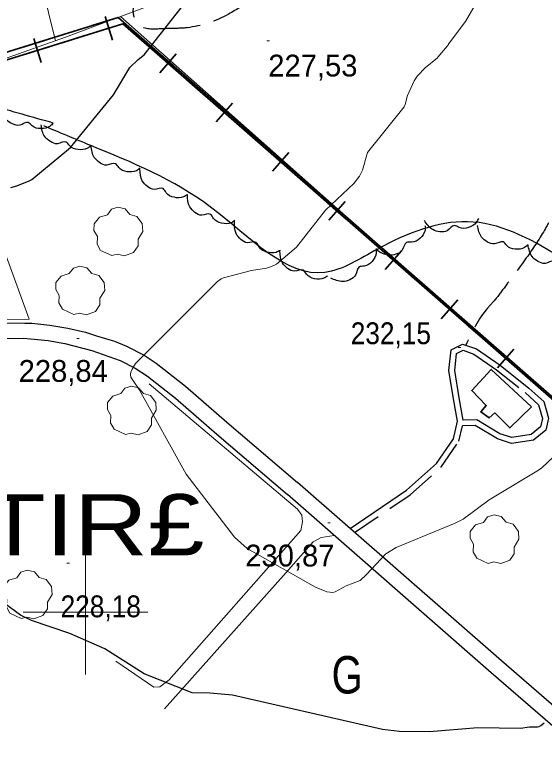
# Model space of a CAD drawing. Extents: x 480269 to 484877, y 4383588 to 4386804.
# Drawn here: x 482971.7 to 483184, y 4384938.8 to 4385239.6 of the extents above; entities that cross this region are included whole.
import ezdxf
from ezdxf.enums import TextEntityAlignment as Align

# ---------------------------------------------------------------- set-up
doc = ezdxf.new("R2010")
doc.units = 0
doc.header["$LTSCALE"] = 3.8
doc.linetypes.add('LONG_DASHED', pattern=[7.5, 6, -1.5])
doc.linetypes.add('MEDIUM_DASHED', pattern=[4.5, 3, -1.5])
for name, color, linetype, lineweight in [('1', 7, 'Continuous', 13), ('27', 7, 'Continuous', 25), ('29', 7, 'Continuous', 13), ('34', 7, 'Continuous', 35), ('37', 7, 'Continuous', 25), ('38', 7, 'Continuous', 25), ('47', 7, 'Continuous', 35), ('51', 7, 'Continuous', 13), ('7', 7, 'Continuous', 13), ('8', 7, 'Continuous', 25), ('9', 7, 'Continuous', 13)]:
    doc.layers.add(name, color=color, linetype=linetype, lineweight=lineweight)
doc.layers.add('31', color=7, linetype='Continuous')
doc.layers.add('5', color=7, linetype='Continuous')

msp = doc.modelspace()

# ---------------------------------------------------------------- linework, layer by layer
at = {"layer": '1'}
for p, q in [((483000, 4385025), (483000, 4384975)), ((482975, 4385000), (483025, 4385000))]:
    msp.add_line(p, q, dxfattribs=at)
at = {"layer": '27'}
for points in [[(482987.06, 4385196.22), (482962.01, 4385203.27), (482933.82, 4385208.75), (482918.16, 4385210.32), (482910.33, 4385217.37), (482911.12, 4385227.55), (482911.12, 4385236.17), (482900.16, 4385244), (482857.87, 4385258.89), (482836.73, 4385270.64), (482824.21, 4385265.15), (482832.82, 4385247.14), (482820.29, 4385239.3), (482767.05, 4385239.3), (482715.37, 4385240.87), (482694.23, 4385249.49), (482675.44, 4385265.94), (482679.36, 4385287.09), (482678.57, 4385302.75), (482650.39, 4385311.37), (482636.29, 4385330.17), (482633.95, 4385351.32), (482617.5, 4385368.55), (482588.53, 4385379.52), (482572.87, 4385393.62), (482558.78, 4385411.63), (482539.21, 4385429.65), (482525.9, 4385448.45), (482516.5, 4385468.82), (482492.23, 4385501.72), (482482.83, 4385522.08), (482488.31, 4385537.75), (482533.73, 4385569.87), (482542.34, 4385576.13)], [(482987.06, 4385196.22), (482985.78, 4385194.99), (482982.12, 4385194.01), (482978.59, 4385195.11), (482977.04, 4385196.45), (482973.66, 4385195.36), (482970.72, 4385195.88), (482968.23, 4385197.59), (482966.17, 4385202.11)], [(483002.19, 4385187.17), (483000.77, 4385186.11), (482997.02, 4385185.57), (482993.65, 4385187.1), (482992.27, 4385188.61), (482988.78, 4385187.94), (482985.93, 4385188.8), (482983.66, 4385190.81), (482982.17, 4385195.54)], [(483727.16, 4385128.45), (483702.11, 4385129.24), (483649.65, 4385135.5), (483626.16, 4385132.37), (483588.58, 4385137.07), (483567.44, 4385128.45), (483561.17, 4385115.92), (483569.79, 4385101.04), (483587.01, 4385090.07), (483591.71, 4385074.4), (483579.96, 4385046.2), (483570.57, 4385028.19), (483559.61, 4385025.84), (483542.38, 4385040.72), (483515.76, 4385050.9), (483496.19, 4385065), (483481.31, 4385072.05), (483441.38, 4385059.52), (483420.24, 4385048.55), (483385, 4385062.65), (483357.6, 4385086.15), (483334.89, 4385110.44), (483327.07, 4385140.2), (483309.84, 4385151.17), (483298.1, 4385151.17), (483281.65, 4385134.72), (483253.47, 4385133.15), (483239.37, 4385137.85), (483220.58, 4385130.8), (483190.05, 4385142.55), (483153.25, 4385156.65), (483117.23, 4385145.69), (483096.09, 4385136.29), (483050.68, 4385162.14), (483002.13, 4385187.2), (482983.34, 4385195.04)], [(483021.92, 4385178.13), (483020.46, 4385177.12), (483016.69, 4385176.71), (483013.38, 4385178.35), (483012.06, 4385179.91), (483008.54, 4385179.36), (483005.72, 4385180.32), (483003.53, 4385182.4), (483002.2, 4385187.18)], [(483040.85, 4385167.49), (483039.33, 4385166.57), (483035.54, 4385166.43), (483032.35, 4385168.29), (483031.13, 4385169.94), (483027.59, 4385169.63), (483024.84, 4385170.78), (483022.8, 4385173.01), (483021.8, 4385177.87)], [(483059.91, 4385157.12), (483058.39, 4385156.2), (483054.6, 4385156.06), (483051.41, 4385157.92), (483050.19, 4385159.57), (483046.65, 4385159.25), (483043.9, 4385160.41), (483041.86, 4385162.64), (483040.86, 4385167.5)], [(483157.65, 4385157.93), (483156.81, 4385156.37), (483153.62, 4385154.32), (483149.93, 4385154.29), (483148.04, 4385155.1), (483145.15, 4385153.02), (483142.2, 4385152.61), (483139.3, 4385153.49), (483135.97, 4385157.16)], [(483078.05, 4385145.16), (483076.46, 4385144.36), (483072.67, 4385144.48), (483069.62, 4385146.56), (483068.52, 4385148.29), (483064.97, 4385148.22), (483062.3, 4385149.57), (483060.42, 4385151.94), (483059.76, 4385156.85)], [(483136.34, 4385154.95), (483136.23, 4385153.17), (483134.19, 4385149.97), (483130.85, 4385148.4), (483128.8, 4385148.34), (483127.04, 4385145.25), (483124.53, 4385143.64), (483121.53, 4385143.22), (483116.97, 4385145.16)], [(483177.55, 4385147.39), (483176.17, 4385146.29), (483172.43, 4385145.63), (483169.02, 4385147.05), (483167.59, 4385148.52), (483164.13, 4385147.74), (483161.24, 4385148.51), (483158.92, 4385150.45), (483157.28, 4385155.13)], [(483116.56, 4385145.9), (483116.65, 4385144.13), (483114.97, 4385140.73), (483111.82, 4385138.8), (483109.79, 4385138.52), (483108.38, 4385135.25), (483106.06, 4385133.38), (483103.13, 4385132.64), (483098.38, 4385134.07)], [(483197.79, 4385139.57), (483196.4, 4385138.46), (483192.66, 4385137.82), (483189.26, 4385139.25), (483187.84, 4385140.73), (483184.37, 4385139.96), (483181.49, 4385140.75), (483179.17, 4385142.69), (483177.55, 4385147.38)], [(483097.16, 4385134.92), (483095.66, 4385133.98), (483091.87, 4385133.77), (483088.65, 4385135.57), (483087.4, 4385137.2), (483083.87, 4385136.82), (483081.1, 4385137.93), (483079.01, 4385140.12), (483077.93, 4385144.96)]]:
    msp.add_spline(points, degree=3, dxfattribs=at)
at = {"layer": '29'}
for points in [[(483010.6, 4385143.05), (483006.06, 4385145.17), (483004.65, 4385147.71), (483004.75, 4385150.69), (483003.38, 4385153.1), (483003.42, 4385155.85), (483005.58, 4385158.45), (483008.77, 4385159.45), (483010.42, 4385161.64), (483012.99, 4385162.47), (483015.85, 4385161.82), (483017.8, 4385159.55), (483020.61, 4385158.73), (483022.74, 4385155.88), (483022.98, 4385152.75), (483021.1, 4385149.6), (483021.1, 4385146.92), (483019.28, 4385144.31), (483015.66, 4385142.97), (483012.89, 4385143.6)], [(482995.31, 4385119.42), (482990.77, 4385121.54), (482989.36, 4385124.08), (482989.46, 4385127.06), (482988.09, 4385129.47), (482988.13, 4385132.22), (482990.29, 4385134.82), (482993.48, 4385135.82), (482995.13, 4385138.01), (482997.7, 4385138.84), (483000.56, 4385138.19), (483002.51, 4385135.92), (483005.32, 4385135.1), (483007.45, 4385132.25), (483007.69, 4385129.12), (483005.81, 4385125.97), (483005.81, 4385123.29), (483003.99, 4385120.68), (483000.37, 4385119.34), (482997.6, 4385119.97)], [(483016.02, 4385071.31), (483011.48, 4385073.43), (483010.07, 4385075.97), (483010.17, 4385078.95), (483008.8, 4385081.36), (483008.84, 4385084.11), (483011, 4385086.71), (483014.19, 4385087.71), (483015.84, 4385089.9), (483018.41, 4385090.73), (483021.27, 4385090.08), (483023.22, 4385087.81), (483026.03, 4385086.99), (483028.16, 4385084.14), (483028.4, 4385081.01), (483026.52, 4385077.86), (483026.52, 4385075.18), (483024.7, 4385072.57), (483021.08, 4385071.23), (483018.31, 4385071.86)], [(483161.53, 4385019.64), (483156.99, 4385021.76), (483155.58, 4385024.3), (483155.68, 4385027.28), (483154.31, 4385029.69), (483154.35, 4385032.44), (483156.51, 4385035.04), (483159.7, 4385036.04), (483161.35, 4385038.23), (483163.92, 4385039.06), (483166.78, 4385038.41), (483168.73, 4385036.14), (483171.54, 4385035.32), (483173.67, 4385032.47), (483173.91, 4385029.34), (483172.03, 4385026.19), (483172.03, 4385023.51), (483170.21, 4385020.9), (483166.59, 4385019.56), (483163.82, 4385020.19)], [(482974.23, 4384997.48), (482969.69, 4384999.6), (482968.28, 4385002.14), (482968.38, 4385005.12), (482967.01, 4385007.53), (482967.05, 4385010.28), (482969.21, 4385012.88), (482972.4, 4385013.88), (482974.05, 4385016.07), (482976.62, 4385016.9), (482979.48, 4385016.25), (482981.43, 4385013.98), (482984.24, 4385013.16), (482986.37, 4385010.31), (482986.61, 4385007.18), (482984.73, 4385004.03), (482984.73, 4385001.35), (482982.91, 4384998.74), (482979.29, 4384997.4), (482976.52, 4384998.03)]]:
    msp.add_lwpolyline(points, close=True, dxfattribs=at)
at = {"layer": '34'}
for p, q in [((483010.82, 4385229.47), (483007.86, 4385239.02)), ((483012.23, 4385238.28), (483002.68, 4385235.31)), ((483012.23, 4385238.28), (483002.68, 4385235.31)), ((483014.11, 4385235.73), (483004.56, 4385232.76)), ((483025.59, 4385226.75), (483018.06, 4385233.33)), ((482982.18, 4385220.57), (482979.22, 4385230.12)), ((482999.79, 4385231.28), (482990.24, 4385228.31)), ((482983.59, 4385229.38), (482974.04, 4385226.41)), ((482983.59, 4385229.38), (482974.04, 4385226.41)), ((482985.47, 4385226.83), (482975.92, 4385223.86)), ((483035.01, 4385219.43), (483027.48, 4385226.01)), ((483035.01, 4385219.43), (483027.48, 4385226.01)), ((483036.89, 4385216.88), (483029.36, 4385223.46)), ((483029.83, 4385216.4), (483036.41, 4385223.93)), ((483048.18, 4385207.02), (483040.65, 4385213.6)), ((483057.59, 4385199.7), (483050.06, 4385206.28)), ((483057.59, 4385199.7), (483050.06, 4385206.28)), ((483059.47, 4385197.15), (483051.94, 4385203.73)), ((483052.42, 4385196.67), (483059, 4385204.2)), ((483070.76, 4385187.29), (483063.23, 4385193.87)), ((483080.18, 4385179.97), (483072.65, 4385186.55)), ((483080.18, 4385179.97), (483072.65, 4385186.55)), ((483075, 4385176.94), (483081.58, 4385184.47)), ((483082.06, 4385177.42), (483074.53, 4385184)), ((483093.35, 4385167.56), (483085.82, 4385174.13)), ((483102.76, 4385160.24), (483095.23, 4385166.82)), ((483102.76, 4385160.24), (483095.23, 4385166.82)), ((483104.64, 4385157.69), (483097.11, 4385164.27)), ((483097.59, 4385157.21), (483104.17, 4385164.74)), ((483115.93, 4385147.82), (483108.4, 4385154.4)), ((483125.35, 4385140.51), (483117.82, 4385147.08)), ((483125.35, 4385140.51), (483117.82, 4385147.08)), ((483127.23, 4385137.96), (483119.7, 4385144.53)), ((483120.17, 4385137.48), (483126.75, 4385145.01)), ((483138.52, 4385128.09), (483130.99, 4385134.67)), ((483147.93, 4385120.77), (483140.4, 4385127.35)), ((483147.93, 4385120.77), (483140.4, 4385127.35)), ((483149.81, 4385118.22), (483142.28, 4385124.8)), ((483142.76, 4385117.75), (483149.34, 4385125.28)), ((483161.1, 4385108.36), (483153.57, 4385114.94)), ((483170.52, 4385101.04), (483162.99, 4385107.62)), ((483170.52, 4385101.04), (483162.99, 4385107.62)), ((483172.4, 4385098.49), (483164.87, 4385105.07)), ((483165.34, 4385098.02), (483171.92, 4385105.55)), ((483183.69, 4385088.63), (483176.16, 4385095.21))]:
    msp.add_line(p, q, dxfattribs=at)
for points in [[(483464.12, 4384844.55), (483013.12, 4385238.55), (482720.12, 4385147.55)], [(483464.12, 4384844.55), (483013.12, 4385238.55), (482720.12, 4385147.55)], [(483466, 4384842), (483015, 4385236), (482722, 4385145)]]:
    msp.add_lwpolyline(points, dxfattribs=at)
at = {"layer": '37'}
for points in [[(482750.83, 4385043.15), (482792.84, 4385058.2), (482913.56, 4385101.78), (482939.57, 4385111.12), (482955.6, 4385115), (482967.37, 4385116.08), (482975.61, 4385116.03), (482978.44, 4385115.95), (482985.74, 4385115.14), (482992.89, 4385114), (482999.97, 4385112.36), (483004.37, 4385110.93), (483011.65, 4385108.69), (483016.47, 4385106.74), (483023.56, 4385103.12), (483028.35, 4385099.96), (483040.15, 4385090.7), (483056.73, 4385076.2), (483085.09, 4385052.01)], [(482752.89, 4385037.24), (482794.96, 4385052.31), (482915.68, 4385095.89), (482941.37, 4385105.12), (482956.63, 4385108.81), (482967.62, 4385109.83), (482975.06, 4385109.91), (482977.98, 4385109.7), (482985.07, 4385109.02), (482991.66, 4385107.85), (483002.53, 4385104.94), (483013.88, 4385101.02), (483019.88, 4385097.89), (483024.85, 4385094.76), (483036.16, 4385085.88), (483052.64, 4385071.47), (483081.03, 4385047.25)], [(483278.04, 4384763.7), (483388.31, 4384775.37), (483396.25, 4384777.5), (483401.8, 4384780.35), (483406.67, 4384784.64), (483410.91, 4384790.59), (483412.8, 4384795.66), (483413.03, 4384800.96), (483412.9, 4384805.24), (483411.9, 4384810.34), (483409.49, 4384815.21), (483404.8, 4384820.61), (483398.46, 4384824.66), (483380.67, 4384830.95), (483329.04, 4384849.79), (483319.89, 4384854.08), (483310.58, 4384858.59), (483303.26, 4384863.02), (483294.69, 4384869.69), (483265.36, 4384895.28), (483166.86, 4384980.49), (483085.09, 4385052.01)], [(483277.39, 4384769.88), (483387.17, 4384781.5), (483394, 4384783.33), (483398.27, 4384785.53), (483402.03, 4384788.83), (483405.38, 4384793.53), (483406.63, 4384796.91), (483406.81, 4384801), (483406.7, 4384804.54), (483405.96, 4384808.33), (483404.27, 4384811.74), (483400.69, 4384815.85), (483395.71, 4384819.03), (483378.57, 4384825.1), (483326.65, 4384844.04), (483317.22, 4384848.47), (483307.61, 4384853.12), (483299.73, 4384857.89), (483290.74, 4384864.89), (483261.29, 4384890.58), (483162.79, 4384975.79), (483081.03, 4385047.25)]]:
    msp.add_lwpolyline(points, dxfattribs=at)
at = {"layer": '38'}
msp.add_lwpolyline([(483106.14, 4385033.6), (483128.84, 4385049.01), (483140.8, 4385059.65), (483147.64, 4385069.6), (483149.27, 4385076.64), (483147.61, 4385085.57), (483145.83, 4385096.92), (483146.75, 4385105.22), (483151.31, 4385107.6), (483156.89, 4385105.64), (483166.32, 4385099.13), (483177.88, 4385089.96), (483183.85, 4385084.49), (483185.81, 4385077.82), (483184.64, 4385073.09), (483179.73, 4385069.06), (483170.92, 4385067.76), (483165.33, 4385069.51), (483156.38, 4385074.9), (483151.22, 4385074.77)], dxfattribs=at)
at = {"layer": '38', "linetype": 'MEDIUM_DASHED'}
msp.add_lwpolyline([(483151.54, 4385077.1), (483149.89, 4385085.96), (483148.16, 4385096.97), (483148.92, 4385103.74), (483151.49, 4385105.08), (483155.83, 4385103.56), (483164.94, 4385097.26), (483176.38, 4385088.2), (483181.81, 4385083.22), (483183.41, 4385077.77), (483182.57, 4385074.39), (483178.76, 4385071.25), (483171.11, 4385070.13), (483166.29, 4385071.64), (483157, 4385077.23)], close=True, dxfattribs=at)
msp.add_lwpolyline([(483107.95, 4385032.02), (483130.27, 4385047.18), (483142.55, 4385058.11), (483149.8, 4385068.65), (483151.22, 4385074.77)], dxfattribs=at)
at = {"layer": '38', "linetype": 'LONG_DASHED'}
for points in [[(483231.71, 4385291.72), (483227.07, 4385289.88), (483224.76, 4385288.84), (483210.03, 4385287.11), (483195.81, 4385285.01), (483189.41, 4385283.56), (483174.85, 4385274.14), (483167.81, 4385267.95), (483162.72, 4385266.81), (483147.6, 4385269.26), (483135.17, 4385269.21), (483119.25, 4385265.45), (483108.31, 4385261.73), (483096.96, 4385258.93), (483089.15, 4385256.51), (483079.32, 4385250.68), (483067.26, 4385245.51), (483057.36, 4385239.88), (483040.77, 4385234.46), (483034.16, 4385234.12), (483030.67, 4385234.03), (483022.01, 4385235.14), (483019.28, 4385239.84), (483021.59, 4385248.25), (483027.91, 4385256.06), (483032.96, 4385259.9), (483035.22, 4385262.44), (483041.85, 4385273.53), (483044.53, 4385281.27), (483044.91, 4385281.85)], [(483224.5, 4385288.79), (483215.18, 4385270.41), (483210.92, 4385259.97), (483207.19, 4385254.06), (483203.43, 4385244.09), (483201.5, 4385230.63), (483197.81, 4385218.11), (483194.75, 4385214.07), (483190.62, 4385208.45), (483188.08, 4385196.33), (483190.37, 4385184.14), (483191.32, 4385176.01), (483191.42, 4385172.87), (483187.92, 4385160.4), (483184.53, 4385153.91), (483177.42, 4385142.89), (483168.21, 4385130.43), (483163.61, 4385124.56), (483161.24, 4385121.93), (483152.6, 4385107.16)]]:
    msp.add_spline(points, degree=3, dxfattribs=at)
at = {"layer": '47'}
msp.add_lwpolyline([(483178.95, 4385082.35), (483170.29, 4385073.92), (483164.19, 4385080), (483162.02, 4385077.94), (483158.65, 4385080.4), (483160.8, 4385082.99), (483154.96, 4385088.98), (483162.79, 4385097.44)], close=True, dxfattribs=at)
at = {"layer": '51'}
msp.add_line((483014.09, 4385239.01), (483086.9, 4385174.35), dxfattribs=at)
for points in [[(482404.1, 4385677.73), (482302.92, 4385714.75), (482302.94, 4385713.84), (482359.86, 4385638.29), (482423.37, 4385556.01), (482487.7, 4385471.02), (482548.28, 4385389.71), (482609.6, 4385302.12), (482658.45, 4385236.36), (482731.86, 4385137.6), (482793.32, 4385159.98), (482893.05, 4385195.69), (482991.91, 4385230.66), (483071.52, 4385260.62), (483095.48, 4385269.3)], [(482888.55, 4385653.3), (482898.36, 4385609.21), (482918.04, 4385522.13), (482930.07, 4385471.8), (482937.62, 4385437.48), (482942.19, 4385414.98), (482947.25, 4385388.98), (482952.06, 4385372.32), (482962.15, 4385333.18), (482987.92, 4385229.25)], [(482942.5, 4385213.18), (482977.38, 4385117.59), (482963.03, 4385117.44), (482951.62, 4385115.72), (482942.17, 4385113.17), (482923.87, 4385106.77), (482898.56, 4385097.91), (482807.23, 4385064.72), (482757.84, 4385047.5), (482755.28, 4385047.9), (482753.59, 4385049.34), (482751.71, 4385051.55), (482745.16, 4385065.2), (482737.85, 4385077), (482727.91, 4385087.2), (482717.9, 4385095.04), (482705.8, 4385100.41), (482691.98, 4385104.02), (482677.18, 4385105.47), (482666.61, 4385104.38), (482649.93, 4385100.31), (482731.86, 4385137.6)], [(483086.9, 4385174.35), (483229.36, 4385048.09), (483347.1, 4384943.87), (483471.81, 4384834.33), (483524.94, 4384677.86), (483563.45, 4384563.55), (483629, 4384366.69), (483674.71, 4384233.19), (483700.1, 4384145.59)], [(483012.13, 4384980.46), (483027.38, 4384970.02), (483029.79, 4384970.18), (483033.55, 4384972.88), (483086.36, 4385032.86), (483087.09, 4385036.23), (483086.77, 4385039), (483085.06, 4385041.31), (483025.55, 4385091.63)], [(483099.82, 4385030.83), (483094.54, 4385030.06), (483091.29, 4385028.32), (483080.47, 4385015.96), (483031.63, 4384961.28)]]:
    msp.add_lwpolyline(points, dxfattribs=at)
at = {"layer": '7'}
for p, q in [((483072.82, 4385229.26), (483073.82, 4385229.26)), ((482996.47, 4385109.84), (482997.47, 4385109.84)), ((483149.55, 4385106.22), (483150.55, 4385106.22)), ((483097.18, 4385035.87), (483098.18, 4385035.87)), ((482992.56, 4385019.74), (482993.56, 4385019.74))]:
    msp.add_line(p, q, dxfattribs=at)
at = {"layer": '8'}
for points in [[(482970.08, 4385170.42), (482972.49, 4385170.98), (482977.43, 4385173.04), (482978.41, 4385173.59), (482993.96, 4385186.42), (483011.2, 4385207.57), (483017.83, 4385218.55), (483021.15, 4385221.68), (483023.48, 4385223.52), (483049.15, 4385256.36), (483050.78, 4385257.8), (483062.76, 4385269.39), (483070.55, 4385284.41), (483071.24, 4385287.17), (483074.13, 4385326.3), (483079.11, 4385336.59), (483080.65, 4385338.92), (483081.85, 4385340.28), (483083.23, 4385341.45), (483108.45, 4385356.67)], [(483184.08, 4384955.51), (483183.26, 4384954.86), (483182.73, 4384954.52), (483182.06, 4384954.18), (483181.92, 4384954.13), (483181.42, 4384953.99), (483180.48, 4384953.91), (483178.21, 4384953.9), (483174.52, 4384953.46), (483157.46, 4384953.61), (483138.03, 4384952.01), (483125.97, 4384952.14), (483119.22, 4384953), (483059, 4384966.83), (483049.95, 4384967.62), (483042.78, 4384967.69), (483023.48, 4384975.36), (483007.71, 4384985.32), (482993.73, 4384991.48), (482978.39, 4384996.73), (482973.89, 4384998.82), (482945.67, 4385019.39)]]:
    msp.add_lwpolyline(points, dxfattribs=at)
at = {"layer": '9'}
for points in [[(483141.23, 4385222.42), (483141.24, 4385222.46), (483141.26, 4385222.48), (483141.31, 4385222.54), (483141.37, 4385222.59), (483141.38, 4385222.6), (483141.39, 4385222.61), (483141.42, 4385222.61), (483145.24, 4385227.23), (483145.61, 4385227.78), (483145.71, 4385227.97), (483145.77, 4385228.06), (483145.92, 4385228.2), (483152.42, 4385236.94), (483152.44, 4385236.95), (483152.46, 4385236.95), (483156.31, 4385243.67)], [(483192.85, 4385067.22), (483183.05, 4385057.98), (483181.77, 4385057.02), (483161.92, 4385045.17), (483151.53, 4385037.41), (483148.27, 4385035.71), (483124.7, 4385026.06), (483120.44, 4385023.43), (483112.77, 4385015.23), (483112.62, 4385015.02), (483110.24, 4385012.79), (483110.23, 4385012.79), (483110.21, 4385012.79), (483104.65, 4385010.58), (483100.21, 4385008.16), (483099.2, 4385007.95), (483096.83, 4385008.22), (483092.25, 4385010.02), (483064.84, 4385025.59), (483059.78, 4385030.17), (483040.35, 4385055.34), (483021.48, 4385089.42), (483018.93, 4385093.1), (483018.25, 4385094.37), (483018.04, 4385095.18), (483018.02, 4385095.59), (483018.14, 4385096.29), (483018.68, 4385097.48), (483020.1, 4385099.74), (483020.53, 4385100.29), (483052.91, 4385132.61), (483054.47, 4385133.7), (483055.36, 4385134.19), (483066.63, 4385137.07), (483072.65, 4385137.98), (483074.69, 4385138.65), (483076.67, 4385139.68), (483084.61, 4385146.4), (483096.32, 4385161.24), (483107.7, 4385171.93), (483109.9, 4385174.9), (483111.16, 4385177.3), (483113.17, 4385184.44), (483127.87, 4385202.75), (483128.23, 4385203.69), (483129.2, 4385207.29), (483131.83, 4385213.11), (483133.24, 4385215.18), (483136.29, 4385218.32), (483141.23, 4385222.42)]]:
    msp.add_lwpolyline(points, dxfattribs=at)

# ---------------------------------------------------------------- texts
at = {"layer": '31', "width": 0.8}
msp.add_text('G', height=15, dxfattribs=at).set_placement((483104.99, 4384967.44), align=Align.CENTER)
at = {"layer": '5', "width": 1.25}
msp.add_text('PONTIR£', height=24.5, dxfattribs=at).set_placement((482870.22, 4385022.88))
at = {"layer": '7'}
for s, p in [('227,53', (483073.32, 4385214.89)), ('228,84', (482973.17, 4385092.43)), ('230,87', (483064.09, 4385018.38))]:
    msp.add_text(s, height=8.75, dxfattribs=at).set_placement(p)
at = {"layer": '7', "width": 0.9}
for s, p in [('232,15', (483106.41, 4385107.54)), ('228,18', (482990.01, 4384998.02))]:
    msp.add_text(s, height=8.75, dxfattribs=at).set_placement(p)

doc.saveas('drawing.dxf')
